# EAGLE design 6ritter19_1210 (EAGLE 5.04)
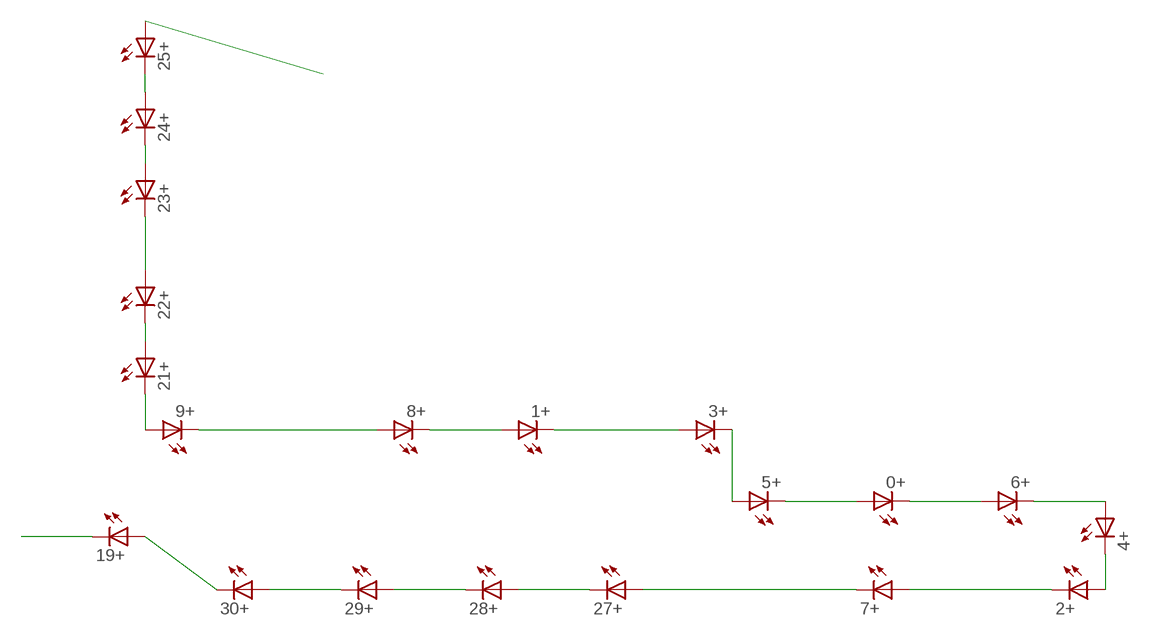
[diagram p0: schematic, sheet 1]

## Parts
0+  LED1210  [1210]
1+  LED1210  [1210]
2+  LED1210  [1210]
3+  LED1210  [1210]
4+  LED1210  [1210]
5+  LED1210  [1210]
6+  LED1210  [1210]
7+  LED1210  [1210]
8+  LED1210  [1210]
9+  LED1210  [1210]
19+  LED1210  [1210]
21+  LED1210  [1210]
22+  LED1210  [1210]
23+  LED1210  [1210]
24+  LED1210  [1210]
25+  LED1210  [1210]
27+  LED1210  [1210]
28+  LED1210  [1210]
29+  LED1210  [1210]
30+  LED1210  [1210]

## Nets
MINUS: 19+.P$2(C)
N$4: 19+.P$1(A) 30+.P$2(C)
N$6: 8+.P$1(A) 9+.P$2(C)
N$7: 29+.P$2(C) 30+.P$1(A)
N$8: 28+.P$2(C) 29+.P$1(A)
N$9: 27+.P$2(C) 28+.P$1(A)
N$12: 2+.P$2(C) 7+.P$1(A)
N$13: 7+.P$2(C) 27+.P$1(A)
N$14: 2+.P$1(A) 4+.P$2(C)
N$15: 4+.P$1(A) 6+.P$2(C)
N$16: 0+.P$2(C) 6+.P$1(A)
N$17: 0+.P$1(A) 5+.P$2(C)
N$18: 3+.P$2(C) 5+.P$1(A)
N$19: 1+.P$2(C) 3+.P$1(A)
N$20: 1+.P$1(A) 8+.P$2(C)
N$23: 9+.P$1(A) 21+.P$2(C)
N$24: 21+.P$1(A) 22+.P$2(C)
N$25: 22+.P$1(A) 23+.P$2(C)
N$26: 24+.P$1(A) 25+.P$2(C)
N$28: 23+.P$1(A) 24+.P$2(C)
PLUS: 25+.P$1(A)

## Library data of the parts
0+ 1+ 2+ 3+ 4+ 5+ 6+ 7+ 8+ 9+ 19+ 21+ 22+ 23+ 24+ 25+ 27+ 28+ 29+ 30+ = led(2):LED: LED

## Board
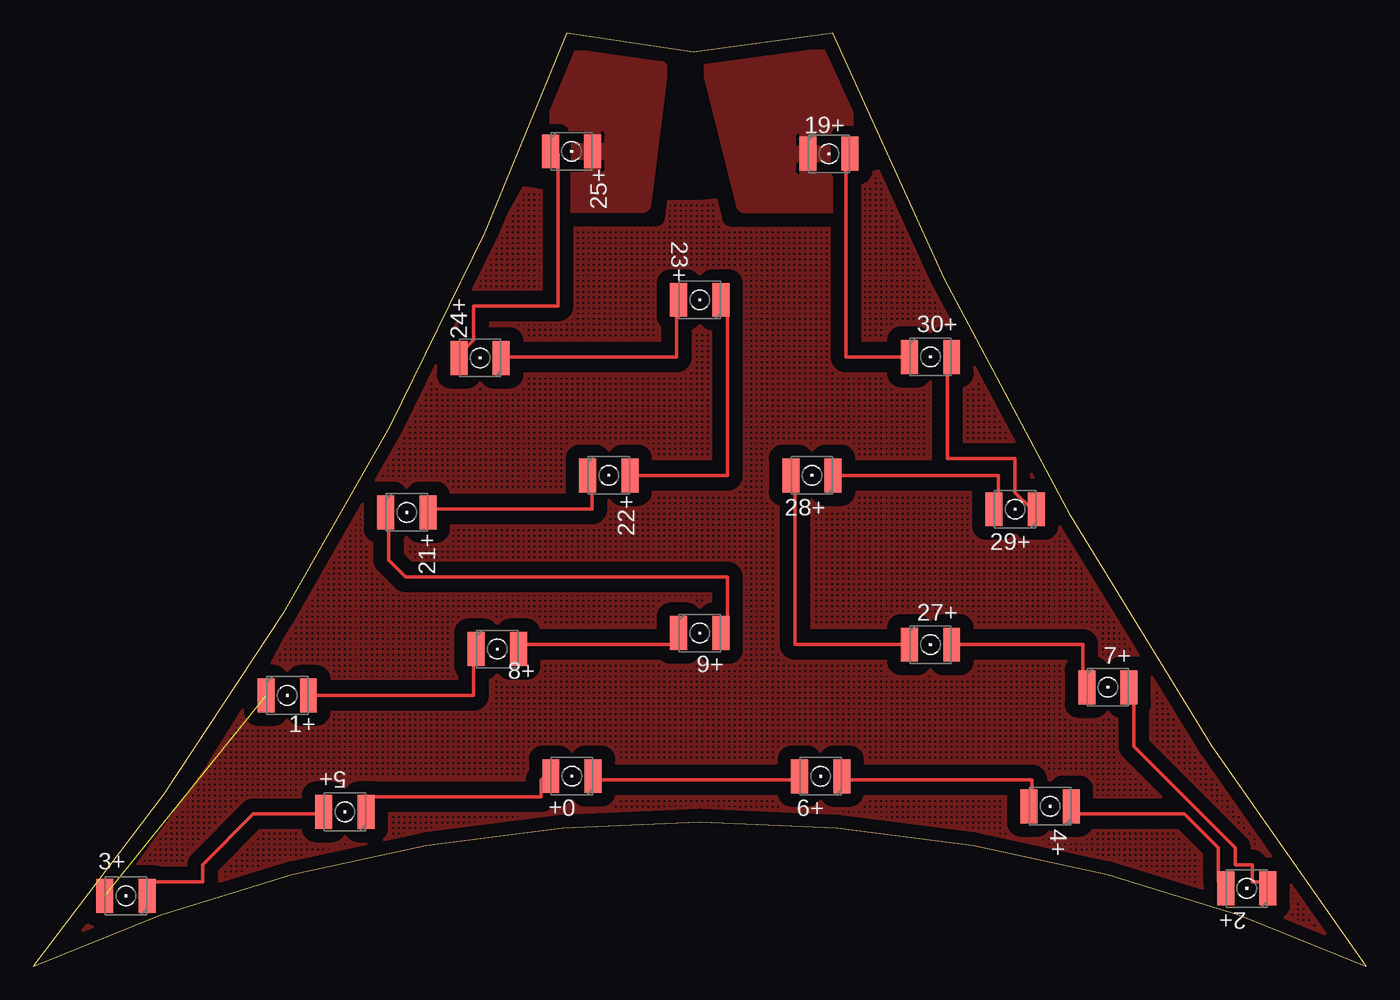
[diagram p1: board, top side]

Size 100 x 70 mm. Coordinates in mm from the lower left corner, seen from the top.
Outline: 0,0 arc-49 100,0 arc-14 60,70 49.53,68.58 40,70 arc-18 0,0
Copper layers (1*16): Top 0.035mm / dielectric 1.5mm / Bottom 0.035mm
Design rules "default": minimum track width 10mil, minimum drill 24mil, track to track 8mil, track to pad 8mil, pad to pad 8mil, via to via 8mil, smd to smd 8mil, copper to edge 40mil, drill to drill 8mil, minimum pad ring 10mil, minimum via ring 8mil, stop-mask expansion 4mil, vias tented up to drill 0mil, thermal gap 10mil

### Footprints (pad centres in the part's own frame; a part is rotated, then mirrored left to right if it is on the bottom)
1210 = smd 1.27 x 2.54: P$1 1.587,0; P$2 -1.587,0

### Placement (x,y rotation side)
0+  40.41,14.26 180 top
1+  19.05,20.32 0 top
2+  91.04,5.84 180 top
3+  6.95,5.28 180 top
4+  76.29,12 180 top
5+  23.38,11.58 180 top
6+  59.07,14.25 180 top
7+  80.62,20.93 0 top
8+  34.81,23.8 0 top
9+  50,25 0 top
19+  59.69,60.96 0 top
21+  28.02,34.05 0 top
22+  43.18,36.83 0 top
23+  50,50 180 top
24+  33.52,45.64 180 top
25+  40.38,61.14 0 top
27+  67.31,24.13 0 top
28+  58.42,36.83 180 top
29+  73.66,34.29 180 top
30+  67.31,45.72 0 top

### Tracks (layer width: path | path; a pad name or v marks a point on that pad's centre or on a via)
MINUS
  pour Top (isolate 0.813, rank 2): 50.8,67.31 53.34,57.15 64.77,57.15 59.69,68.58
N$1
  pour Top (isolate 1.016, rank 3, hatched): 36.83,58.42 25.4,38.1 arc-19 2.54,1.27 arc-46 99.91,-0.06 arc-13 63.5,59.69 arc-28
N$4
  Top 0.254: 66.04,45.72 30+.P$2 60.96,45.72 60.96,60.96 19+.P$1
N$6
  Top 0.254: 8+.P$1 36.83,24.13 48.26,24.13 9+.P$2
N$7
  Top 0.254: 29+.P$2 74.93,34.29 73.66,35.56 73.66,38.1 68.58,38.1 68.58,45.72 30+.P$1
N$8
  Top 0.254: 59.69,36.83 28+.P$2 72.39,36.83 72.39,34.29 29+.P$1
N$9
  Top 0.254: 66.04,24.13 27+.P$2 57.15,24.13 57.15,36.83 28+.P$1
N$12
  Top 0.254: 2+.P$2 92.71,6.35 91.44,6.35 91.44,7.62 90.17,7.62 90.17,8.89 82.55,16.51 82.55,20.32 7+.P$1
N$13
  Top 0.254: 68.58,24.13 27+.P$1 78.74,24.13 78.74,21.59 7+.P$2
N$14
  Top 0.254: 4+.P$2 77.47,11.43 86.36,11.43 88.9,8.89 88.9,6.35 2+.P$1
N$15
  Top 0.254: 6+.P$2 60.96,13.97 74.93,13.97 74.93,12.7 4+.P$1
N$16
  Top 0.254: 0+.P$2 41.91,13.97 57.15,13.97 6+.P$1
N$17
  Top 0.254: 5+.P$2 25.4,12.7 38.1,12.7 38.1,13.97 39.37,15.24 0+.P$1
N$18
  Top 0.254: 3+.P$2 8.89,6.35 12.7,6.35 12.7,7.62 16.51,11.43 21.59,11.43 5+.P$1
N$19  (1 unrouted)
N$20
  Top 0.254: 20.32,20.32 1+.P$1 33.02,20.32 33.02,22.86 8+.P$2
N$23
  Top 0.254: 21+.P$2 26.67,33.02 26.67,30.48 27.94,29.21 52.07,29.21 52.07,25.4 9+.P$1
N$24
  Top 0.254: 21+.P$1 29.21,34.29 41.91,34.29 41.91,36.83 22+.P$2
N$25
  Top 0.254: 44.45,36.83 22+.P$1 52.07,36.83 52.07,49.53 23+.P$2
N$26
  Top 0.254: 24+.P$1 31.75,45.72 33.02,46.99 33.02,49.53 39.37,49.53 39.37,60.96 25+.P$2
N$28
  Top 0.254: 24+.P$2 35.56,45.72 48.26,45.72 48.26,49.53 23+.P$1
PLUS
  pour Top (isolate 0.813): 38.1,68.58 46.99,67.31 45.72,57.15 38.1,57.15 31.75,58.42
